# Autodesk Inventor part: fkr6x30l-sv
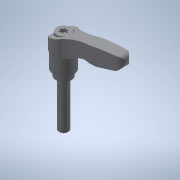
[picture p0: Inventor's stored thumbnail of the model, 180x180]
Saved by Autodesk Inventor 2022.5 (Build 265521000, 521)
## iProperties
Created: 2017-09
Part Number: fkr6x30l-sv
Material: 一般
Document SubType Name: Modeling
Designer: imaocorp
Density: 1 g/cm^3
Appearance: 既定
Author: imaocorp
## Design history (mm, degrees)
node "fkr6x30l-sv.x_t1"
node "fkr6x30l-sv"
node "Base1"
